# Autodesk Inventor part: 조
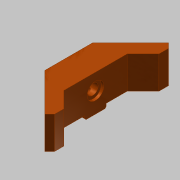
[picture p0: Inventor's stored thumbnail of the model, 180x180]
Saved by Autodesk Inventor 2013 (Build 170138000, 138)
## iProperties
Created: 2019-04
Part Number: 조
Material: 알루미늄 6061
Document SubType Name: Modeling
Designer: mduedu
Density: 1 g/cm^3
Author: mduedu
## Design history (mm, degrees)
sketch "스케치1"
  geometry: L1 (45.962, 0)-(0, -45.962); L2 (0, -45.962)-(-45.962, 0); L3 (-45.962, 0)-(0, 45.962); L4 (0, 45.962)-(45.962, 0); L5 (45.962, 0)-(-45.962, 0); L6 (0, -45.962)-(0, 45.962); 1 further point
  constraints: 12 end point, 2 midpoint, 2 parallel, 2 perpendicular, 1 horizontal
  dimensions: "d0" = 65 distance of L1.end L2.end
extrude "돌출1" new body sketch "스케치1" distance "d2" = 27; taper "d3" = 0 deg
chamfer "모따기1" distance "d4" = 25; stored, may be unused: second distance "d5" = 2, angle "d6" = 45 deg
sketch "스케치2"
  geometry: L1 (-17.678, 28.284)-(-45.962, 0) reference; L2 (-17.678, 28.284)-(17.678, 28.284) reference; L3 (45.962, 0)-(17.678, 28.284) reference; L4 (-45.962, 0)-(0, -45.962) reference; L5 (0, -45.962)-(45.962, 0) reference; L6 (-23.536, 8.284)-(23.536, 8.284); L7 (-23.536, 8.284)-(-38.891, -7.071); L8 (38.891, -7.071)-(23.536, 8.284); 1 further point
  constraints: 6 end point, 3 parallel, 2 point on line
  dimensions: "d7" = 20 distance between parallel lines of L6 L2; "d8" = 10 distance between parallel lines of L1 L7; "d9" = 10 distance between parallel lines of L3 L8
extrude "돌출2" cut sketch "스케치2" stored distance "d10" = 27; taper "d11" = 0 deg
sketch "스케치3"
  geometry: L1 (63.64, -27)-(63.64, 0) reference; L2 (56.569, -27)-(63.64, -27) reference; L3 (-28.284, -27)-(-28.284, 0) reference; L4 (-28.284, -27)-(-21.213, -27) reference; L5 (63.64, -27)-(25.678, -27); L6 (25.678, -27)-(25.678, -24); L7 (25.678, -24)-(63.64, -24); L8 (63.64, -24)-(63.64, -27); L9 (-28.284, -27)-(9.678, -27); L10 (9.678, -27)-(9.678, -24); L11 (9.678, -24)-(-28.284, -24); L12 (-28.284, -24)-(-28.284, -27); L13 (41.213, 0)-(-5.858, 0) reference; L14 (17.678, -27)-(17.678, 0)
  constraints: 18 end point, 4 parallel, 2 horizontal, 2 perpendicular, 1 midpoint, 1 symmetric about line
  dimensions: "d12" = 3 distance between parallel lines of L5 L7; "d14" = 16 distance between parallel lines of L10 L6
extrude "돌출3" cut sketch "스케치3" stored distance "d15" = 27; taper "d16" = 0 deg
sketch "스케치4"
  geometry: L1 (31.536, -27)-(15.536, -27) reference; L2 (31.536, -24)-(47.071, -24) reference; 3 further points
  constraints: 1 midpoint, 1 vertical alignment
  dimensions: "d17" = 12 distance from line of L2 point (23.536, -12)
hole "구멍1" sketch "스케치4" at (23.536, -12) diameter "d18" = 8; stored, may be unused: countersink angle "d22" = 90 deg, drill point angle "d24" = 118 deg; dims "d19" = 6, "d20" = 12.5, "d21" = 2, "d23" = 14
node "작업 평면1"
sketch "스케치5"
  geometry: L1 (0, -15)-(0, 0); L2 (-50, -4)-(50, -4); L3 (50, -4)-(50, -1.75); L4 (-50, -1.75)-(-50, -4); L5 (12, -1.75)-(12, -2.75); L6 (12, -2.75)-(-12, -2.75); L7 (-12, -2.75)-(-12, -1.75); L8 (50, -1.75)-(12, -1.75); L9 (-12, -1.75)-(-50, -1.75); C1 r 4 at (0, 0) reference; 2 further points
  constraints: 18 end point, 4 parallel, 2 midpoint, 2 vertical, 2 vertical alignment, 1 collinear, 1 horizontal, 1 perpendicular, 1 tangent
  dimensions: "d26" = 2.5 diameter of L6 L2; "d28" = 4.5 diameter of L8 L2; "d29" = 24 distance of L5.end L6.end; "d30" = 100 distance between parallel lines of L3 L4
revolve "회전1" sketch "스케치5" stored, may be unused: angle "d31" = 90 deg
chamfer "모따기2" distance "d32" = 5; stored, may be unused: second distance "d33" = 2, angle "d34" = 45 deg
chamfer "모따기3" distance "d35" = 1; stored, may be unused: second distance "d36" = 2, angle "d37" = 45 deg
node "솔리드1"
other parameters: "d25" = -5
